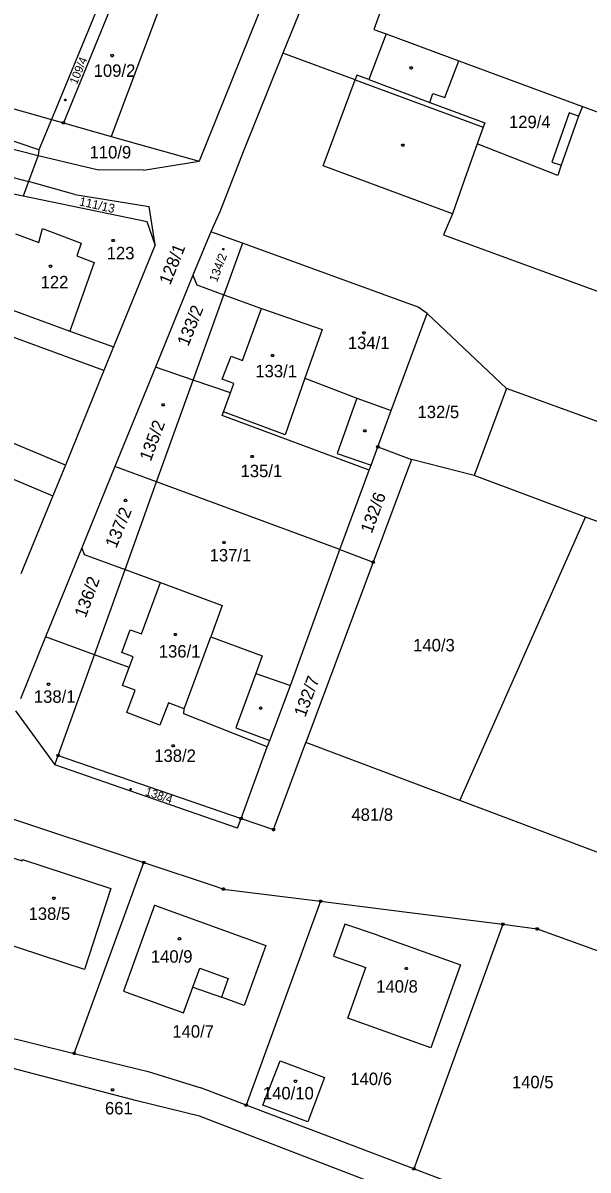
# Model space of a CAD drawing. Extents: x -634640 to -629202, y -1196156 to -1190068.
# Drawn here: x -631267.3 to -631190.1, y -1192913 to -1192756.2 of the extents above; entities that cross this region are included whole.
import ezdxf

# ---------------------------------------------------------------- set-up
doc = ezdxf.new("R2010")
doc.units = 0
for name, color, linetype in [('Vrstva 1', 7, 'Continuous'), ('Vrstva 2', 7, 'Continuous'), ('Vrstva 3', 7, 'Continuous'), ('Vrstva 4', 7, 'Continuous'), ('Vrstva 5', 7, 'Continuous'), ('Vrstva 7', 7, 'Continuous'), ('Vrstva 8', 7, 'Continuous')]:
    doc.layers.add(name, color=color, linetype=linetype)

msp = doc.modelspace()

# ---------------------------------------------------------------- linework, layer by layer
at = {"layer": 'Vrstva 1'}
for p, q in [((-631221.05, -1192720.23), (-631243.22, -1192775.11)), ((-631215.45, -1192720.07), (-631231.76, -1192760.36)), ((-631214.04, -1192742.55), (-631219.35, -1192757.09)), ((-631256.12, -1192751.82), (-631263.39, -1192769.4)), ((-631254.55, -1192752.26), (-631261.74, -1192769.87)), ((-631248.54, -1192753.93), (-631255.23, -1192771.71)), ((-631217.67, -1192757.71), (-631220.05, -1192763.96)), ((-631219.35, -1192757.09), (-631217.67, -1192757.71)), ((-631217.67, -1192757.71), (-631207.72, -1192761.39)), ((-631231.76, -1192760.36), (-631237.13, -1192773.62)), ((-631221.9, -1192764), (-631231.76, -1192760.36)), ((-631286.91, -1192762.74), (-631263.39, -1192769.4)), ((-631209.64, -1192766.41), (-631207.72, -1192761.39)), ((-631207.72, -1192761.39), (-631190.83, -1192767.63)), ((-631226.25, -1192775.73), (-631221.9, -1192764)), ((-631221.66, -1192763.35), (-631221.9, -1192764)), ((-631220.05, -1192763.96), (-631221.66, -1192763.35)), ((-631265.11, -1192773.56), (-631288.17, -1192765.84)), ((-631211.68, -1192767.08), (-631211.27, -1192765.85)), ((-631211.27, -1192765.85), (-631209.64, -1192766.41)), ((-631211.68, -1192767.08), (-631204.2, -1192769.88)), ((-631289.13, -1192768.17), (-631265.22, -1192774.34)), ((-631192.66, -1192768.52), (-631195.02, -1192775.25)), ((-631191.38, -1192768.95), (-631192.66, -1192768.52)), ((-631190.83, -1192767.63), (-631191.38, -1192768.95)), ((-631190.83, -1192767.63), (-631179.89, -1192771.67)), ((-631263.39, -1192769.4), (-631265.11, -1192773.56)), ((-631263.39, -1192769.4), (-631261.74, -1192769.87)), ((-631261.74, -1192769.87), (-631255.23, -1192771.71)), ((-631204.4, -1192770.45), (-631205.22, -1192772.75)), ((-631204.2, -1192769.88), (-631204.4, -1192770.45)), ((-631255.23, -1192771.71), (-631243.22, -1192775.11)), ((-631265.11, -1192773.56), (-631265.22, -1192774.34)), ((-631237.13, -1192773.62), (-631240.37, -1192782.03)), ((-631194.2, -1192777.08), (-631205.22, -1192772.75)), ((-631265.22, -1192774.34), (-631266.53, -1192777.88)), ((-631265.22, -1192774.34), (-631256.95, -1192776.29)), ((-631250.84, -1192776.31), (-631243.22, -1192775.11)), ((-631195.02, -1192775.25), (-631193.74, -1192775.67)), ((-631275.65, -1192775.56), (-631266.53, -1192777.88)), ((-631250.84, -1192776.31), (-631256.95, -1192776.29)), ((-631208.61, -1192782.32), (-631226.25, -1192775.73)), ((-631193.74, -1192775.67), (-631194.2, -1192777.08)), ((-631267.27, -1192779.89), (-631276.72, -1192777.95)), ((-631266.53, -1192777.88), (-631267.27, -1192779.89)), ((-631260.22, -1192779.64), (-631266.53, -1192777.88)), ((-631250.33, -1192783.38), (-631267.27, -1192779.89)), ((-631260.22, -1192779.64), (-631250.06, -1192781.29)), ((-631249.24, -1192786.53), (-631250.06, -1192781.29)), ((-631240.37, -1192782.03), (-631241.63, -1192784.76)), ((-631208.61, -1192782.32), (-631209.81, -1192785.17)), ((-631265.1, -1192786.23), (-631264.6, -1192784.32)), ((-631264.6, -1192784.32), (-631259.35, -1192786.29)), ((-631249.24, -1192786.53), (-631250.33, -1192783.38)), ((-631268.29, -1192785.04), (-631266.59, -1192785.68)), ((-631266.59, -1192785.68), (-631265.1, -1192786.23)), ((-631241.63, -1192784.76), (-631244.06, -1192790.69)), ((-631237.31, -1192786.33), (-631241.63, -1192784.76)), ((-631209.81, -1192785.17), (-631138.96, -1192811.11)), ((-631259.35, -1192786.29), (-631259.93, -1192788.03)), ((-631249.24, -1192786.53), (-631254.9, -1192800.46)), ((-631237.31, -1192786.33), (-631239.84, -1192793.36)), ((-631213.27, -1192795.07), (-631237.31, -1192786.33)), ((-631257.56, -1192788.95), (-631260.88, -1192798.34)), ((-631259.93, -1192788.03), (-631257.56, -1192788.95)), ((-631244.06, -1192790.69), (-631249.2, -1192803.26)), ((-631244.06, -1192790.69), (-631243.53, -1192792.01)), ((-631243.53, -1192792.01), (-631239.84, -1192793.36)), ((-631244.03, -1192805.03), (-631239.84, -1192793.36)), ((-631239.84, -1192793.36), (-631234.7, -1192795.25)), ((-631234.7, -1192795.25), (-631226.42, -1192798.09)), ((-631212.05, -1192795.91), (-631213.27, -1192795.07)), ((-631256.23, -1192803.72), (-631276.09, -1192796.41)), ((-631216.96, -1192809.17), (-631212.05, -1192795.91)), ((-631212.05, -1192795.91), (-631201.2, -1192806.16)), ((-631260.88, -1192798.34), (-631254.9, -1192800.46)), ((-631226.42, -1192798.09), (-631228.76, -1192804.77)), ((-631254.9, -1192800.46), (-631256.23, -1192803.72)), ((-631249.2, -1192803.26), (-631254.75, -1192816.82)), ((-631244.03, -1192805.03), (-631249.2, -1192803.26)), ((-631256.23, -1192803.72), (-631261.48, -1192816.65)), ((-631249.03, -1192818.93), (-631244.03, -1192805.03)), ((-631238.93, -1192806.78), (-631244.03, -1192805.03)), ((-631228.76, -1192804.77), (-631221.69, -1192807.49)), ((-631201.2, -1192806.16), (-631205.66, -1192818.05)), ((-631153.67, -1192823.45), (-631201.2, -1192806.16)), ((-631239.88, -1192809.37), (-631238.93, -1192806.78)), ((-631221.69, -1192807.49), (-631216.96, -1192809.17)), ((-631261.48, -1192816.65), (-631279.18, -1192809.27)), ((-631240.08, -1192809.87), (-631239.88, -1192809.37)), ((-631218.81, -1192814.16), (-631216.96, -1192809.17)), ((-631219.97, -1192817.32), (-631240.08, -1192809.87)), ((-631280.95, -1192813.42), (-631263.19, -1192820.82)), ((-631219.73, -1192816.66), (-631218.81, -1192814.16)), ((-631218.81, -1192814.16), (-631214.21, -1192815.87)), ((-631214.21, -1192815.87), (-631219.43, -1192829.88)), ((-631205.66, -1192818.05), (-631214.21, -1192815.87)), ((-631261.48, -1192816.65), (-631263.19, -1192820.82)), ((-631254.75, -1192816.82), (-631259.25, -1192827.92)), ((-631249.03, -1192818.93), (-631254.75, -1192816.82)), ((-631224.01, -1192828.18), (-631219.97, -1192817.32)), ((-631219.97, -1192817.32), (-631219.73, -1192816.66)), ((-631253.33, -1192830.9), (-631249.03, -1192818.93)), ((-631224.01, -1192828.18), (-631249.03, -1192818.93)), ((-631190.41, -1192823.74), (-631205.66, -1192818.05)), ((-631263.19, -1192820.82), (-631267.58, -1192831.48)), ((-631207.62, -1192862.47), (-631190.41, -1192823.74)), ((-631151.85, -1192838.13), (-631190.41, -1192823.74)), ((-631259.25, -1192827.92), (-631264.19, -1192840.11)), ((-631259.25, -1192827.92), (-631258.91, -1192828.84)), ((-631230.75, -1192846.73), (-631224.01, -1192828.18)), ((-631224.01, -1192828.18), (-631219.43, -1192829.88)), ((-631258.91, -1192828.84), (-631253.33, -1192830.9)), ((-631219.43, -1192829.88), (-631228.63, -1192854.55)), ((-631257.52, -1192842.55), (-631253.33, -1192830.9)), ((-631253.33, -1192830.9), (-631248.51, -1192832.69)), ((-631248.51, -1192832.69), (-631240.05, -1192835.81)), ((-631240.05, -1192835.81), (-631241.63, -1192840.09)), ((-631264.19, -1192840.11), (-631267.63, -1192848.59)), ((-631257.52, -1192842.55), (-631264.19, -1192840.11)), ((-631241.63, -1192840.09), (-631234.59, -1192842.69)), ((-631262.46, -1192856.31), (-631257.52, -1192842.55)), ((-631252.78, -1192844.29), (-631257.52, -1192842.55)), ((-631234.59, -1192842.69), (-631235.47, -1192845.1)), ((-631253.67, -1192846.73), (-631252.78, -1192844.29)), ((-631235.47, -1192845.1), (-631230.75, -1192846.73)), ((-631251.94, -1192847.39), (-631253.67, -1192846.73)), ((-631253.11, -1192850.43), (-631251.94, -1192847.39)), ((-631233.58, -1192854.26), (-631230.75, -1192846.73)), ((-631268.31, -1192850.22), (-631262.93, -1192857.61)), ((-631248.57, -1192852.16), (-631253.11, -1192850.43)), ((-631247.41, -1192849.12), (-631248.57, -1192852.16)), ((-631245.27, -1192849.95), (-631247.41, -1192849.12)), ((-631245.31, -1192850.64), (-631245.27, -1192849.95)), ((-631233.9, -1192855.15), (-631245.31, -1192850.64)), ((-631237.48, -1192864.92), (-631233.9, -1192855.15)), ((-631233.9, -1192855.15), (-631233.58, -1192854.26)), ((-631233.06, -1192866.44), (-631228.63, -1192854.55)), ((-631207.62, -1192862.47), (-631228.63, -1192854.55)), ((-631262.93, -1192857.61), (-631262.46, -1192856.31)), ((-631262.46, -1192856.31), (-631237.48, -1192864.92)), ((-631237.96, -1192866.23), (-631262.93, -1192857.61)), ((-631166.26, -1192878.06), (-631207.62, -1192862.47)), ((-631273.75, -1192863.28), (-631250.78, -1192870.94)), ((-631237.96, -1192866.23), (-631237.48, -1192864.92)), ((-631237.48, -1192864.92), (-631233.06, -1192866.44)), ((-631260.27, -1192897.02), (-631250.78, -1192870.94)), ((-631250.78, -1192870.94), (-631240.9, -1192874.23)), ((-631236.26, -1192875.03), (-631226.64, -1192876.24)), ((-631249.31, -1192876.76), (-631253.57, -1192888.52)), ((-631226.64, -1192876.24), (-631236.78, -1192904.1)), ((-631226.64, -1192876.24), (-631214.42, -1192877.78)), ((-631214.42, -1192877.78), (-631201.71, -1192879.38)), ((-631223.3, -1192879.37), (-631224.87, -1192883.72)), ((-631218.86, -1192880.88), (-631223.3, -1192879.37)), ((-631201.71, -1192879.38), (-631213.87, -1192912.8)), ((-631201.71, -1192879.38), (-631197.04, -1192880.02)), ((-631197.04, -1192880.02), (-631178.32, -1192886.73)), ((-631218.86, -1192880.88), (-631207.5, -1192884.93)), ((-631224.87, -1192883.72), (-631220.44, -1192885.3)), ((-631207.5, -1192884.93), (-631211.56, -1192896.26)), ((-631222.92, -1192892.23), (-631220.44, -1192885.3)), ((-631244.06, -1192887.96), (-631240.18, -1192889.36)), ((-631285.25, -1192890.88), (-631260.27, -1192897.02)), ((-631211.56, -1192896.26), (-631222.92, -1192892.23)), ((-631251.75, -1192903.51), (-631287.05, -1192894.28)), ((-631260.27, -1192897.02), (-631250.17, -1192899.51)), ((-631234.5, -1192904.08), (-631232.15, -1192898.05)), ((-631232.15, -1192898.05), (-631226.09, -1192900.33)), ((-631250.17, -1192899.51), (-631243, -1192901.74)), ((-631226.09, -1192900.33), (-631228.35, -1192906.37)), ((-631236.78, -1192904.1), (-631243, -1192901.74)), ((-631243.17, -1192905.59), (-631251.75, -1192903.51)), ((-631213.87, -1192912.8), (-631236.78, -1192904.1)), ((-631228.35, -1192906.37), (-631234.5, -1192904.08)), ((-631184.25, -1192928.26), (-631243.17, -1192905.59)), ((-631190.98, -1192921.49), (-631213.87, -1192912.8))]:
    msp.add_line(p, q, dxfattribs=at)
for points in [[(-631274.53, -1192868.46), (-631267.39, -1192870.73), (-631267.33, -1192870.54), (-631255.28, -1192874.49), (-631258.9, -1192885.58), (-631270.88, -1192881.64), (-631269.4, -1192876.94), (-631276.51, -1192874.62), (-631274.53, -1192868.46)], [(-631240.9, -1192874.23), (-631239.88, -1192874.57), (-631236.26, -1192875.03)], [(-631249.31, -1192876.76), (-631234.11, -1192882.28), (-631237.07, -1192890.48), (-631240.18, -1192889.36)], [(-631253.57, -1192888.52), (-631245.35, -1192891.5), (-631244.06, -1192887.96)]]:
    msp.add_lwpolyline(points, dxfattribs=at)
at = {"layer": 'Vrstva 3'}
for points in [[(-631255.02, -1192760.53), (-631254.93, -1192760.68), (-631255.02, -1192760.83), (-631255.2, -1192760.83), (-631255.29, -1192760.68), (-631255.2, -1192760.53), (-631255.02, -1192760.53)], [(-631261.43, -1192766.64), (-631261.369, -1192766.74), (-631261.43, -1192766.84), (-631261.55, -1192766.84), (-631261.611, -1192766.74), (-631261.55, -1192766.64), (-631261.43, -1192766.64)], [(-631254.86, -1192785.79), (-631254.77, -1192785.94), (-631254.86, -1192786.09), (-631255.04, -1192786.09), (-631255.13, -1192785.94), (-631255.04, -1192785.79), (-631254.86, -1192785.79)], [(-631239.86, -1192787.04), (-631239.799, -1192787.14), (-631239.86, -1192787.24), (-631239.98, -1192787.24), (-631240.041, -1192787.14), (-631239.98, -1192787.04), (-631239.86, -1192787.04)], [(-631220.61, -1192798.43), (-631220.52, -1192798.58), (-631220.61, -1192798.73), (-631220.79, -1192798.73), (-631220.88, -1192798.58), (-631220.79, -1192798.43), (-631220.61, -1192798.43)], [(-631248.05, -1192808.24), (-631247.96, -1192808.39), (-631248.05, -1192808.54), (-631248.23, -1192808.54), (-631248.32, -1192808.39), (-631248.23, -1192808.24), (-631248.05, -1192808.24)], [(-631235.87, -1192815.3), (-631235.78, -1192815.45), (-631235.87, -1192815.6), (-631236.05, -1192815.6), (-631236.14, -1192815.45), (-631236.05, -1192815.3), (-631235.87, -1192815.3)], [(-631253.18, -1192821.3), (-631253.09, -1192821.45), (-631253.18, -1192821.6), (-631253.36, -1192821.6), (-631253.45, -1192821.45), (-631253.36, -1192821.3), (-631253.18, -1192821.3)], [(-631239.73, -1192827.07), (-631239.64, -1192827.22), (-631239.73, -1192827.37), (-631239.91, -1192827.37), (-631240, -1192827.22), (-631239.91, -1192827.07), (-631239.73, -1192827.07)], [(-631263.7, -1192846.43), (-631263.61, -1192846.58), (-631263.7, -1192846.73), (-631263.88, -1192846.73), (-631263.97, -1192846.58), (-631263.88, -1192846.43), (-631263.7, -1192846.43)], [(-631246.66, -1192854.84), (-631246.57, -1192854.99), (-631246.66, -1192855.14), (-631246.84, -1192855.14), (-631246.93, -1192854.99), (-631246.84, -1192854.84), (-631246.66, -1192854.84)], [(-631252.5, -1192860.81), (-631252.439, -1192860.91), (-631252.5, -1192861.01), (-631252.62, -1192861.01), (-631252.681, -1192860.91), (-631252.62, -1192860.81), (-631252.5, -1192860.81)]]:
    msp.add_lwpolyline(points, dxfattribs=at)
at = {"layer": 'Vrstva 4'}
for p, q in [((-631221.9, -1192764), (-631204.4, -1192770.45)), ((-631220.05, -1192763.96), (-631211.68, -1192767.08)), ((-631191.38, -1192768.95), (-631193.74, -1192775.67)), ((-631205.22, -1192772.75), (-631206.94, -1192777.6)), ((-631206.94, -1192777.6), (-631208.61, -1192782.32)), ((-631270.06, -1192794.98), (-631260.88, -1192798.34)), ((-631237.3, -1192802.32), (-631234.7, -1192795.25)), ((-631240.05, -1192804.91), (-631238.85, -1192801.75)), ((-631238.85, -1192801.75), (-631237.3, -1192802.32)), ((-631238.46, -1192805.5), (-631240.05, -1192804.91)), ((-631228.76, -1192804.77), (-631231.45, -1192812.48)), ((-631238.93, -1192806.78), (-631238.46, -1192805.5)), ((-631221.69, -1192807.49), (-631224.36, -1192815.05)), ((-631231.45, -1192812.48), (-631239.88, -1192809.37)), ((-631224.36, -1192815.05), (-631219.73, -1192816.66)), ((-631251.08, -1192839.69), (-631248.51, -1192832.69)), ((-631253.78, -1192842.25), (-631252.62, -1192839.13)), ((-631252.62, -1192839.13), (-631251.08, -1192839.69)), ((-631245.27, -1192849.95), (-631241.63, -1192840.09)), ((-631252.24, -1192842.82), (-631253.78, -1192842.25)), ((-631252.78, -1192844.29), (-631252.24, -1192842.82)), ((-631235.47, -1192845.1), (-631238.19, -1192852.52)), ((-631238.19, -1192852.52), (-631233.58, -1192854.26))]:
    msp.add_line(p, q, dxfattribs=at)
msp.add_lwpolyline([(-631244.06, -1192887.96), (-631243.12, -1192885.36), (-631239.24, -1192886.77), (-631240.18, -1192889.36)], dxfattribs=at)
at = {"layer": 'Vrstva 5'}
for points in [[(-631214.15, -1192762.22), (-631214.06, -1192762.37), (-631214.15, -1192762.52), (-631214.33, -1192762.52), (-631214.42, -1192762.37), (-631214.33, -1192762.22), (-631214.15, -1192762.22)], [(-631215.29, -1192772.76), (-631215.2, -1192772.91), (-631215.29, -1192773.06), (-631215.47, -1192773.06), (-631215.56, -1192772.91), (-631215.47, -1192772.76), (-631215.29, -1192772.76)], [(-631263.44, -1192789.32), (-631263.35, -1192789.47), (-631263.44, -1192789.62), (-631263.62, -1192789.62), (-631263.71, -1192789.47), (-631263.62, -1192789.32), (-631263.44, -1192789.32)], [(-631233.11, -1192801.51), (-631233.02, -1192801.66), (-631233.11, -1192801.81), (-631233.29, -1192801.81), (-631233.38, -1192801.66), (-631233.29, -1192801.51), (-631233.11, -1192801.51)], [(-631220.47, -1192811.8), (-631220.38, -1192811.95), (-631220.47, -1192812.1), (-631220.65, -1192812.1), (-631220.74, -1192811.95), (-631220.65, -1192811.8), (-631220.47, -1192811.8)], [(-631246.38, -1192839.63), (-631246.29, -1192839.78), (-631246.38, -1192839.93), (-631246.56, -1192839.93), (-631246.65, -1192839.78), (-631246.56, -1192839.63), (-631246.38, -1192839.63)], [(-631234.72, -1192849.68), (-631234.63, -1192849.83), (-631234.72, -1192849.98), (-631234.9, -1192849.98), (-631234.99, -1192849.83), (-631234.9, -1192849.68), (-631234.72, -1192849.68)], [(-631262.98, -1192875.68), (-631262.89, -1192875.83), (-631262.98, -1192875.98), (-631263.16, -1192875.98), (-631263.25, -1192875.83), (-631263.16, -1192875.68), (-631262.98, -1192875.68)], [(-631245.79, -1192881.2), (-631245.7, -1192881.35), (-631245.79, -1192881.5), (-631245.97, -1192881.5), (-631246.06, -1192881.35), (-631245.97, -1192881.2), (-631245.79, -1192881.2)], [(-631214.82, -1192885.28), (-631214.73, -1192885.43), (-631214.82, -1192885.58), (-631215, -1192885.58), (-631215.09, -1192885.43), (-631215, -1192885.28), (-631214.82, -1192885.28)], [(-631229.97, -1192900.68), (-631229.88, -1192900.83), (-631229.97, -1192900.98), (-631230.15, -1192900.98), (-631230.24, -1192900.83), (-631230.15, -1192900.68), (-631229.97, -1192900.68)]]:
    msp.add_lwpolyline(points, dxfattribs=at)
at = {"layer": 'Vrstva 8'}
for points in [[(-631261.65, -1192769.72), (-631261.56, -1192769.87), (-631261.65, -1192770.02), (-631261.83, -1192770.02), (-631261.92, -1192769.87), (-631261.83, -1192769.72), (-631261.65, -1192769.72)], [(-631218.72, -1192814.01), (-631218.63, -1192814.16), (-631218.72, -1192814.31), (-631218.9, -1192814.31), (-631218.99, -1192814.16), (-631218.9, -1192814.01), (-631218.72, -1192814.01)], [(-631219.34, -1192829.73), (-631219.25, -1192829.88), (-631219.34, -1192830.03), (-631219.52, -1192830.03), (-631219.61, -1192829.88), (-631219.52, -1192829.73), (-631219.34, -1192829.73)], [(-631262.37, -1192856.16), (-631262.28, -1192856.31), (-631262.37, -1192856.46), (-631262.55, -1192856.46), (-631262.64, -1192856.31), (-631262.55, -1192856.16), (-631262.37, -1192856.16)], [(-631237.39, -1192864.77), (-631237.3, -1192864.92), (-631237.39, -1192865.07), (-631237.57, -1192865.07), (-631237.66, -1192864.92), (-631237.57, -1192864.77), (-631237.39, -1192864.77)], [(-631232.97, -1192866.29), (-631232.88, -1192866.44), (-631232.97, -1192866.59), (-631233.15, -1192866.59), (-631233.24, -1192866.44), (-631233.15, -1192866.29), (-631232.97, -1192866.29)], [(-631250.69, -1192870.79), (-631250.6, -1192870.94), (-631250.69, -1192871.09), (-631250.87, -1192871.09), (-631250.96, -1192870.94), (-631250.87, -1192870.79), (-631250.69, -1192870.79)], [(-631239.79, -1192874.42), (-631239.7, -1192874.57), (-631239.79, -1192874.72), (-631239.97, -1192874.72), (-631240.06, -1192874.57), (-631239.97, -1192874.42), (-631239.79, -1192874.42)], [(-631226.55, -1192876.09), (-631226.46, -1192876.24), (-631226.55, -1192876.39), (-631226.73, -1192876.39), (-631226.82, -1192876.24), (-631226.73, -1192876.09), (-631226.55, -1192876.09)], [(-631201.62, -1192879.23), (-631201.53, -1192879.38), (-631201.62, -1192879.53), (-631201.8, -1192879.53), (-631201.89, -1192879.38), (-631201.8, -1192879.23), (-631201.62, -1192879.23)], [(-631196.95, -1192879.87), (-631196.86, -1192880.02), (-631196.95, -1192880.17), (-631197.13, -1192880.17), (-631197.22, -1192880.02), (-631197.13, -1192879.87), (-631196.95, -1192879.87)], [(-631260.18, -1192896.87), (-631260.09, -1192897.02), (-631260.18, -1192897.17), (-631260.36, -1192897.17), (-631260.45, -1192897.02), (-631260.36, -1192896.87), (-631260.18, -1192896.87)], [(-631254.96, -1192901.85), (-631254.87, -1192902), (-631254.96, -1192902.15), (-631255.14, -1192902.15), (-631255.23, -1192902), (-631255.14, -1192901.85), (-631254.96, -1192901.85)], [(-631236.69, -1192903.95), (-631236.6, -1192904.1), (-631236.69, -1192904.25), (-631236.87, -1192904.25), (-631236.96, -1192904.1), (-631236.87, -1192903.95), (-631236.69, -1192903.95)], [(-631213.78, -1192912.65), (-631213.69, -1192912.8), (-631213.78, -1192912.95), (-631213.96, -1192912.95), (-631214.05, -1192912.8), (-631213.96, -1192912.65), (-631213.78, -1192912.65)]]:
    msp.add_lwpolyline(points, dxfattribs=at)

# ---------------------------------------------------------------- texts
at = {"layer": 'Vrstva 2'}
for s, height, rotation, p in [('109/4', 1.14, 67.66632, (-631259.92, -1192764.702)), ('111/13', 1.2, 347.38431, (-631259.679, -1192781.131)), ('128/1', 1.7, 68.29657, (-631247.175, -1192792.125)), ('134/2', 1.19, 69.55708, (-631240.784, -1192791.712)), ('133/2', 1.7, 68.18198, (-631244.704, -1192800.505)), ('135/2', 1.7, 69.38519, (-631249.832, -1192816.222)), ('132/6', 1.7, 69.72896, (-631219.633, -1192826.074)), ('137/2', 1.7, 67.55173, (-631254.55, -1192828.107)), ('136/2', 1.7, 69.78626, (-631258.724, -1192837.591)), ('132/7', 1.7, 69.72896, (-631228.719, -1192851.187)), ('138/4', 1.14, 341.54014, (-631250.688, -1192861.71))]:
    msp.add_text(s, height=height, rotation=rotation, dxfattribs=at).set_placement(p)
for s, p in [('109/2', (-631257.627, -1192763.58)), ('129/4', (-631200.887, -1192770.59)), ('110/9', (-631258.187, -1192774.73)), ('123', (-631255.847, -1192788.51)), ('122', (-631264.877, -1192792.48)), ('134/1', (-631222.897, -1192800.78)), ('133/1', (-631235.537, -1192804.64)), ('132/5', (-631213.38, -1192810.22)), ('135/1', (-631237.557, -1192818.28)), ('137/1', (-631241.787, -1192829.8)), ('136/1', (-631248.727, -1192842.93)), ('140/3', (-631213.977, -1192842.09)), ('138/1', (-631265.797, -1192849.12)), ('138/2', (-631249.347, -1192857.19)), ('138/5', (-631266.52, -1192878.78)), ('140/9', (-631249.814, -1192884.63)), ('140/8', (-631219.024, -1192888.72)), ('140/7', (-631246.88, -1192894.87)), ('140/6', (-631222.564, -1192901.35)), ('140/5', (-631200.484, -1192901.79)), ('140/10', (-631234.509, -1192903.31))]:
    msp.add_text(s, height=1.7, dxfattribs=at).set_placement(p)
at = {"layer": 'Vrstva 7'}
msp.add_text('481/8', height=1.7, dxfattribs=at).set_placement((-631222.411, -1192865.24))
at = {"layer": 'Vrstva 8'}
msp.add_text('661', height=1.7, dxfattribs=at).set_placement((-631256.083, -1192905.36))

doc.saveas('drawing.dxf')
